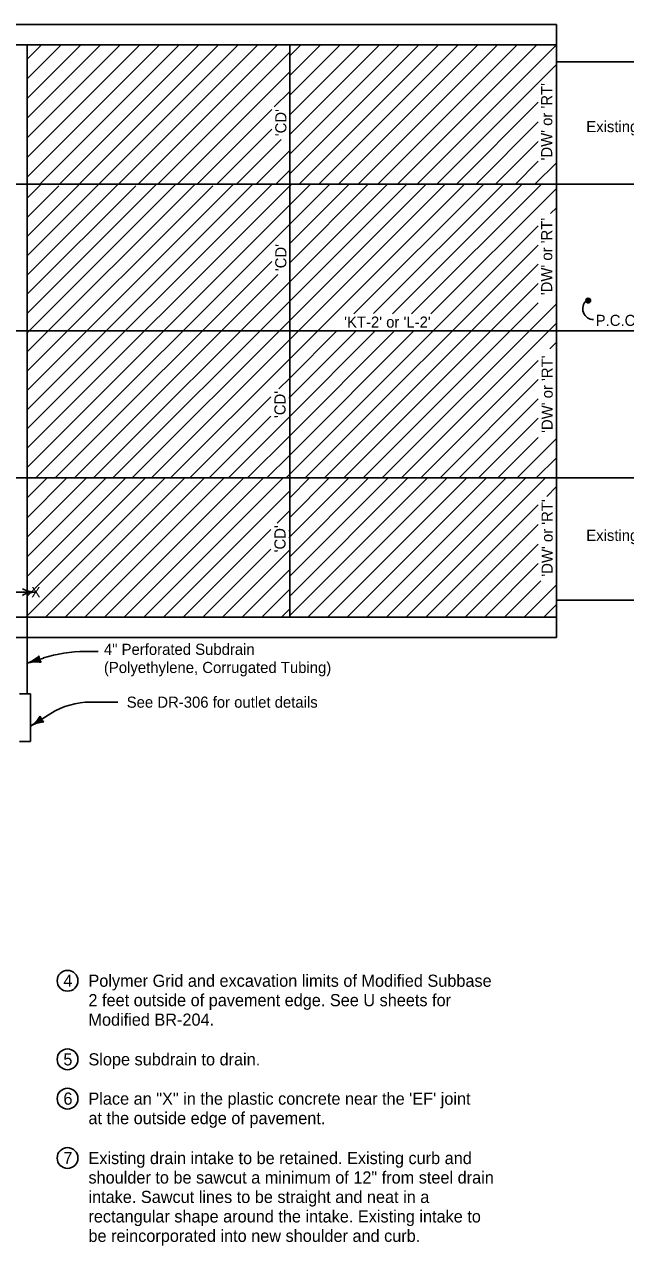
# Model space of a CAD drawing. Extents: x 5546 to 81668, y 3174 to 15999.
# Drawn here: x 23262 to 24175, y 11561 to 13417 of the extents above; entities that cross this region are included whole.
import ezdxf

# ---------------------------------------------------------------- set-up
doc = ezdxf.new("R2010")
doc.units = 0
doc.layers.add('PS_BOLT', color=7, linetype='Continuous')
doc.layers.add('PS_DIM', color=7, linetype='Continuous')

msp = doc.modelspace()

# ---------------------------------------------------------------- linework, layer by layer
at = {"layer": 'PS_BOLT'}
for p, q in [((24069.8, 13221.6), (24069.8, 13263.2)), ((24069.8, 13174), (24069.8, 12727.8)), ((23600.9, 12727.8), (23664.9, 12791.7)), ((23630.1, 12727.8), (23664.9, 12762.5)), ((22068.7, 12727.8), (24069.8, 12727.8)), ((23659.3, 12727.8), (23664.9, 12733.3)), ((23279.1, 12554.2), (23247.6, 12554.2)), ((23374, 12464.1), (23354.2, 12464.1)), ((23404.1, 12387.1), (23362.4, 12387.1)), ((23302, 12369.7), (23271.3, 12350.5))]:
    msp.add_line(p, q, dxfattribs=at)
for centre, radius, start, end in [((24126.2, 12984.7), 16.5, 131.3092, 270), ((23354.2, 12257.5), 206.6, 90, 107.8594), ((23362.4, 12273.5), 113.6, 90, 122.0832)]:
    msp.add_arc(centre, radius, start, end, dxfattribs=at)
at = {"layer": 'PS_DIM'}
for p, q in [((22132.4, 13416.5), (24069.8, 13416.6)), ((24069.8, 13416.6), (24069.8, 13360)), ((22855.1, 13385.6), (24069.8, 13385.6)), ((23266.2, 13174), (23266.2, 13385.6)), ((23266.2, 13385.6), (23266.2, 13174)), ((23266.2, 13184.6), (23467.2, 13385.6)), ((23266.2, 13214.4), (23437.3, 13385.6)), ((23266.2, 13244.3), (23407.5, 13385.6)), ((23266.2, 13274.1), (23377.6, 13385.6)), ((23266.2, 13304), (23347.8, 13385.6)), ((23266.2, 13333.8), (23317.9, 13385.6)), ((23266.2, 13363.7), (23288.1, 13385.6)), ((23285.5, 13174), (23497, 13385.6)), ((23315.3, 13174), (23526.9, 13385.6)), ((23345.2, 13174), (23556.7, 13385.6)), ((23375, 13174), (23586.6, 13385.6)), ((23404.9, 13174), (23616.4, 13385.6)), ((23434.7, 13174), (23646.2, 13385.6)), ((23664.9, 13219.5), (23830.9, 13385.6)), ((23664.9, 13338.9), (23711.5, 13385.6)), ((23664.9, 13368.7), (23681.7, 13385.6)), ((23664.9, 13189.7), (23860.8, 13385.6)), ((23664.9, 13385.6), (23664.9, 12727.8)), ((23664.9, 13279.2), (23771.2, 13385.6)), ((23664.9, 13309.1), (23741.4, 13385.6)), ((23664.9, 13249.4), (23801.1, 13385.6)), ((23679.1, 13174), (23890.6, 13385.6)), ((23708.9, 13174), (23920.4, 13385.6)), ((23738.8, 13174), (23950.3, 13385.6)), ((23768.6, 13174), (23980.1, 13385.6)), ((23798.5, 13174), (24010, 13385.6)), ((23828.3, 13174), (24039.8, 13385.6)), ((23858.2, 13174), (24069.7, 13385.6)), ((24069.8, 13174), (24069.8, 13385.6)), ((23464.5, 13174), (23664.9, 13374.3)), ((24069.8, 13360), (24331.1, 13360)), ((24069.8, 13174), (24069.8, 13360)), ((23494.4, 13174), (23664.9, 13344.5)), ((23888, 13174), (24069.8, 13355.8)), ((23641.4, 13291.2), (23664.9, 13314.7)), ((23524.2, 13174), (23637.6, 13287.4)), ((23917.9, 13174), (24042.3, 13298.5)), ((23947.7, 13174), (24042.3, 13268.6)), ((23554.1, 13174), (23637.6, 13257.6)), ((23583.9, 13174), (23651.7, 13241.8)), ((23977.5, 13174), (24042.3, 13238.8)), ((23613.8, 13174), (23664.9, 13225.1)), ((24007.4, 13174), (24042.3, 13209)), ((23643.6, 13174), (23664.9, 13195.3)), ((24037.2, 13174), (24069.8, 13206.6)), ((24076.4, 13174), (22021.8, 13174)), ((23266.2, 12727.8), (23266.2, 13174)), ((23266.2, 12802.1), (23638.1, 13174)), ((23266.2, 12919), (23521.2, 13174)), ((23266.2, 12860.5), (23579.7, 13174)), ((23266.2, 12831.3), (23608.9, 13174)), ((23266.2, 13035.9), (23404.3, 13174)), ((23266.2, 12977.4), (23462.8, 13174)), ((23266.2, 12948.2), (23492, 13174)), ((23266.2, 13152.7), (23287.5, 13174)), ((23266.2, 13094.3), (23345.9, 13174)), ((23266.2, 13065.1), (23375.1, 13174)), ((23266.2, 12772.9), (23664.9, 13171.6)), ((23266.2, 12889.8), (23548, 13171.6)), ((23266.2, 13006.6), (23431.1, 13171.6)), ((23266.2, 13123.5), (23314.2, 13171.6)), ((23664.9, 13171.6), (23667.3, 13174)), ((23664.9, 13142.4), (23696.5, 13174)), ((23664.9, 13113.1), (23725.8, 13174)), ((23664.9, 13025.5), (23813.4, 13174)), ((23664.9, 12908.6), (23930.3, 13174)), ((23664.9, 12996.3), (23842.6, 13174)), ((23664.9, 12937.8), (23901.1, 13174)), ((23664.9, 12967), (23871.9, 13174)), ((23664.9, 13054.7), (23784.2, 13174)), ((23664.9, 13083.9), (23755, 13174)), ((23762.3, 12976.9), (23959.5, 13174)), ((23792.1, 12977.4), (23988.7, 13174)), ((23820.8, 12976.9), (24018, 13174)), ((23850, 12976.9), (24047.2, 13174)), ((24069.8, 13174), (24366.1, 13174)), ((23879.2, 12976.9), (24069.8, 13167.4)), ((23266.2, 12743.7), (23664.9, 13142.4)), ((24060.8, 13129.3), (24069.8, 13138.2)), ((23279.5, 12727.8), (23664.9, 13113.1)), ((23664.9, 12733.3), (24042.3, 13110.7)), ((23664.9, 13083.9), (23664.9, 13083.9)), ((23688.5, 12727.8), (24042.3, 13081.5)), ((23308.7, 12727.8), (23637.6, 13056.7)), ((23664.9, 13054.7), (23664.9, 13054.7)), ((23717.8, 12727.8), (24042.3, 13052.3)), ((23337.9, 12727.8), (23646.9, 13036.8)), ((23367.1, 12727.8), (23664.9, 13025.5)), ((23747, 12727.8), (24042.3, 13023.1)), ((23396.3, 12727.8), (23664.9, 12996.3)), ((23776.2, 12727.8), (24042.3, 12993.9)), ((23805.4, 12727.8), (24069.8, 12992.1)), ((22039.6, 12950.9), (24398.5, 12950.9)), ((23425.6, 12727.8), (23664.9, 12967)), ((23663.5, 12848.8), (23765.6, 12950.9)), ((23663.5, 12819.6), (23794.8, 12950.9)), ((23664.9, 12791.7), (23824, 12950.9)), ((23664.9, 12762.5), (23853.2, 12950.9)), ((23664.9, 12879.4), (23736.4, 12950.9)), ((23834.6, 12727.8), (24069.8, 12962.9)), ((23454.8, 12727.8), (23664.9, 12937.8)), ((24060, 12923.9), (24069.8, 12933.7)), ((23484, 12727.8), (23664.9, 12908.6)), ((23863.9, 12727.8), (24042.3, 12906.2)), ((23648.5, 12863), (23664.9, 12879.4)), ((23893.1, 12727.8), (24042.3, 12877)), ((23513.2, 12727.8), (23636.2, 12850.7)), ((23663.5, 12848.8), (23664.9, 12850.2)), ((23922.3, 12727.8), (24042.3, 12847.8)), ((23542.4, 12727.8), (23636.2, 12821.5)), ((23571.7, 12727.8), (23664.9, 12821)), ((23951.5, 12727.8), (24042.3, 12818.5)), ((23980.7, 12727.8), (24042.3, 12789.3)), ((24010, 12727.8), (24069.8, 12787.6)), ((24039.2, 12727.8), (24069.8, 12758.3)), ((23264.3, 12516.2), (23475.8, 12727.8)), ((23266.2, 12727.8), (23266.2, 12516.2)), ((23266.2, 12727.3), (23266.6, 12727.8)), ((23266.2, 12547.9), (23446, 12727.8)), ((23266.2, 12577.8), (23416.1, 12727.8)), ((23266.2, 12607.6), (23386.3, 12727.8)), ((23266.2, 12637.5), (23356.4, 12727.8)), ((23266.2, 12667.3), (23326.6, 12727.8)), ((23266.2, 12697.2), (23296.7, 12727.8)), ((23294.1, 12516.2), (23505.7, 12727.8)), ((23324, 12516.2), (23535.5, 12727.8)), ((23353.8, 12516.2), (23565.4, 12727.8)), ((23383.7, 12516.2), (23595.2, 12727.8)), ((23413.5, 12516.2), (23625.1, 12727.8)), ((23443.4, 12516.2), (23654.9, 12727.8)), ((23663.5, 12636.5), (23754.8, 12727.8)), ((23664.9, 12518.5), (23874.1, 12727.8)), ((23664.9, 12548.3), (23844.3, 12727.8)), ((23664.9, 12578.2), (23814.5, 12727.8)), ((23664.9, 12608), (23784.6, 12727.8)), ((23664.9, 12697.6), (23695.1, 12727.8)), ((23664.9, 12727.8), (23664.9, 12516.2)), ((23664.9, 12667.7), (23724.9, 12727.8)), ((23692.5, 12516.2), (23904, 12727.8)), ((23722.3, 12516.2), (23933.8, 12727.8)), ((23752.2, 12516.2), (23963.7, 12727.8)), ((23782, 12516.2), (23993.5, 12727.8)), ((23811.9, 12516.2), (24023.4, 12727.8)), ((23841.7, 12516.2), (24053.2, 12727.8)), ((24069.8, 12727.8), (24366.1, 12727.8)), ((24069.8, 12516.2), (24069.8, 12727.8)), ((23473.2, 12516.2), (23664.9, 12707.9)), ((24055, 12699.7), (24069.8, 12714.5)), ((23645.8, 12659), (23664.9, 12678)), ((23871.5, 12516.2), (24042.3, 12687)), ((23901.4, 12516.2), (24042.3, 12657.1)), ((23503.1, 12516.2), (23636.2, 12649.4)), ((23663.5, 12646.8), (23664.9, 12648.2)), ((23532.9, 12516.2), (23636.2, 12619.5)), ((23562.8, 12516.2), (23664.9, 12618.3)), ((23931.2, 12516.2), (24042.3, 12627.3)), ((23961.1, 12516.2), (24042.3, 12597.5)), ((23592.6, 12516.2), (23664.9, 12588.5)), ((23990.9, 12516.2), (24046.2, 12571.5)), ((24020.8, 12516.2), (24069.8, 12565.2)), ((23622.5, 12516.2), (23664.9, 12558.6)), ((24069.8, 12541.8), (24331.1, 12541.8)), ((24069.8, 12485.2), (24069.8, 12541.8)), ((23652.3, 12516.2), (23664.9, 12528.8)), ((24050.6, 12516.2), (24069.8, 12535.4)), ((22855, 12516.2), (24069.8, 12516.2)), ((23266.2, 12516.2), (23266.2, 12399.9)), ((22547.3, 12485.2), (24069.8, 12485.2)), ((23290.9, 12454.1), (23266.2, 12446.2)), ((23266.2, 12446.2), (23285.1, 12452.3)), ((23254.8, 12399.9), (23271.3, 12399.9)), ((23271.3, 12399.9), (23271.3, 12327.2)), ((23271.3, 12350.5), (23288.1, 12361)), ((23254.8, 12327.2), (23271.3, 12327.2))]:
    msp.add_line(p, q, dxfattribs=at)
for points in [[(23266.2, 13174), (23266.2, 13174)], [(24117.8, 12993.8), (24119, 12994.3), (24120.9, 12994.9), (24121.3, 12996.8), (24121, 12998.5), (24119.8, 13000.1), (24118, 12999.9), (24116.1, 12999.6), (24115.2, 12998.1), (24115, 12996.5), (24116.1, 12994.4), (24117.5, 12994.3), (24119.4, 12994.7), (24121, 12996), (24120.9, 12997.8), (24119.7, 12999.2), (24118, 12999.4), (24116.1, 12999), (24115.8, 12997.9), (24115.4, 12996.6), (24116.3, 12995.1), (24117.7, 12995.1), (24119.3, 12995.4), (24120.5, 12996.3), (24119.9, 12997.8), (24118.7, 12998.8), (24117.1, 12998.8), (24116.7, 12998), (24116.2, 12997), (24117, 12995.7), (24118.1, 12995.5), (24119.2, 12996), (24119.3, 12997.2), (24118.7, 12998), (24117.6, 12998.3), (24117.1, 12997.9), (24116.8, 12997.2), (24117.4, 12996.3), (24118.1, 12996.1), (24118.9, 12996.5), (24118.7, 12997.2), (24118.2, 12997.6), (24117.4, 12997.6), (24117.5, 12997), (24118.1, 12996.7)], [(23285.8, 12448.6), (23284, 12451.9), (23283.6, 12455.7), (23280, 12452.3), (23273.8, 12448.6), (23281.5, 12449.3), (23285.1, 12448.9), (23283.3, 12451.7), (23282.9, 12454.1), (23280.5, 12451.8), (23277.1, 12449.7), (23281.4, 12449.8), (23283.7, 12449.8), (23282.4, 12452.7), (23280, 12450.6), (23282.4, 12450.7), (23282.1, 12451.7), (23281.2, 12451)], [(23289.8, 12357.7), (23287.2, 12360.4), (23285.8, 12364), (23283.2, 12359.8), (23278.1, 12354.7), (23285.4, 12357.3), (23289, 12357.8), (23286.6, 12360.1), (23285.6, 12362.3), (23283.8, 12359.5), (23281.1, 12356.6), (23285.2, 12357.8), (23287.5, 12358.3), (23285.4, 12360.8), (23283.6, 12358.2), (23285.9, 12358.8), (23285.4, 12359.7), (23284.7, 12358.9)]]:
    msp.add_lwpolyline(points, dxfattribs=at)
for centre, radius in [((24118.1, 12997.1), 3.62), ((23327.6, 11963.8), 15.8), ((23327.6, 11844.4), 15.8), ((23327.6, 11784.7), 15.8), ((23327.6, 11694.5), 15.8)]:
    msp.add_circle(centre, radius, dxfattribs=at)
for centre, radius, start, end in [((23279.1, 12596.7), 42.5, 241.9275, 270), ((23279.1, 12511.7), 42.5, 90, 118.0725), ((23252.7, 12488), 43.9, 287.8585, 315.9309), ((23279.6, 12404.4), 43.9, 79.786, 107.8585), ((23301.2, 12457.5), 17, 180.1251, 215.5918), ((23248, 12387.7), 43.9, 302.0841, 330.1566), ((23294.6, 12313.3), 43.9, 94.0116, 122.0841), ((23302.5, 12370), 17, 194.3508, 229.8175)]:
    msp.add_arc(centre, radius, start, end, dxfattribs=at)

# ---------------------------------------------------------------- texts
at = {"layer": 'PS_BOLT'}
for s, height, p in [("'DW' or 'RT'", 16.884, (24063.4, 13210)), ("'CD'", 16.88, (23659.8, 13246.8)), ("'DW' or 'RT'", 16.884, (24063.4, 13005.3)), ("'CD'", 16.88, (23659.8, 13041.8)), ("'DW' or 'RT'", 16.884, (24064.1, 12796.1)), ("'CD'", 16.88, (23658.5, 12818.7)), ("'DW' or 'RT'", 16.884, (24064.1, 12577.7)), ("'CD'", 16.88, (23658.5, 12614.6))]:
    msp.add_text(s, height=height, rotation=90, dxfattribs=at).set_placement(p)
for s, height, p in [('Existing Shoulder', 16.884, (24115.1, 13253)), ("'KT-2' or 'L-2'", 16.884, (23747.5, 12956)), ('P.C.C. or Composite', 16.884, (24129.4, 12958.6)), ('Existing Shoulder', 16.884, (24115.1, 12632)), ('X', 16.1, (23272.3, 12546.1)), ('4" Perforated Subdrain ', 16.884, (23382.8, 12458.9)), ('(Polyethylene, Corrugated Tubing)', 16.884, (23382.8, 12431.3)), ('See DR-306 for outlet details', 16.884, (23417.4, 12378.6)), ('4', 18.5, (23321.2, 11954.6)), ('Polymer Grid and excavation limits of Modified Subbase ', 18.466, (23359.3, 11954.6)), ('2 feet outside of pavement edge. See U sheets for ', 18.466, (23359.3, 11925.1)), ('Modified BR-204.', 18.466, (23359.3, 11895.5)), ('Slope subdrain to drain.', 18.466, (23359.3, 11835.2)), ('5', 18.5, (23321.2, 11835.2)), ('6', 18.5, (23321.3, 11775.5)), ('Place an "X" in the plastic concrete near the \'EF\' joint ', 18.466, (23359.3, 11775.5)), ('at the outside edge of pavement.', 18.466, (23359.3, 11745.9)), ('7', 18.5, (23321.2, 11685.2)), ('Existing drain intake to be retained. Existing curb and ', 18.466, (23359.3, 11685.2)), ('shoulder to be sawcut a minimum of 12" from steel drain ', 18.466, (23359.3, 11655.7)), ('intake. Sawcut lines to be straight and neat in a ', 18.466, (23359.3, 11626.2)), ('rectangular shape around the intake. Existing intake to ', 18.466, (23359.3, 11596.6)), ('be reincorporated into new shoulder and curb.', 18.466, (23359.3, 11567.1))]:
    msp.add_text(s, height=height, dxfattribs=at).set_placement(p)

doc.saveas('drawing.dxf')
